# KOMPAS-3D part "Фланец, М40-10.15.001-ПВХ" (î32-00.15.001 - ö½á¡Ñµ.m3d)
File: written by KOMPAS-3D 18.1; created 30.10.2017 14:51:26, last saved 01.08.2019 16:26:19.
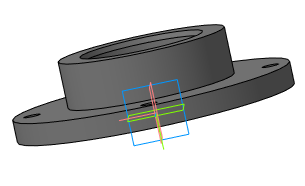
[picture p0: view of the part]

Document properties: Автор: Милов; Организация: Милов; Полное имя файла: D:\Magna\Магна Ins\Магна ins 32\М32-00.15.001 - Фланец.m3d

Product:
- Part/product: Фланец  | designation М40-10.15.001-ПВХ
    Материал: Полипропилен  ГОСТ 26996-86 (density 900 kg/m3)
    Масса: 0.962205
    Раздел спецификации: Детали
    Форматы листов документа: A3
- Part/product: Переходной фланец  | designation М40-00.15.001
    Материал: Полипропилен  ГОСТ 26996-86 (density 900 kg/m3)
    Масса: 0.815286
    Раздел спецификации: Детали
    Форматы листов документа: A3
- Part/product: Переходной фланец  | designation М40-00.15.002
    Материал: Полипропилен  ГОСТ 26996-86 (density 900 kg/m3)
    Масса: 1.3652
    Раздел спецификации: Детали
    Форматы листов документа: A3
- Part/product: Фланец  | designation М32-00.15.001
    Материал: Полипропилен  ГОСТ 26996-86 (density 900 kg/m3)
    Масса: 0.816359
    Раздел спецификации: Детали
    Форматы листов документа: A3
    source file: М32-00.15.001 - Фланец.cdw

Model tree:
1. Эскиз:1
2. Операция вращения:1
     Угол 1 = 360
3. Эскиз:2  (with: Операция вращения:1)
4. Вырезать элемент выдавливания:1
     Расстояние 1 = 30
5. Массив по концентрической сетке:1  (with: Вырезать элемент выдавливания:1, Эскиз:2)  (4 pattern instances)
     Шаг 2 = 360
6. Фаска:1  (with: Операция вращения:1)
     Угол = 45; Длина 1 = 4; Длина 2 = 4
7. Эскиз:3
8. Вырезать элемент выдавливания:2  (labels: Полипропилен  ГОСТ 26996-86; ..\Магна ins 40\3Д\М40-00.15.000 - Корпус М40.a3d)
     Расстояние 1 = 5
9. Вырезать элемент выдавливания:1  (with: Эскиз:2)  (1 pattern instances)
     N 1 = 1; Шаг 1 = 10; Шаг 2 = 360; Номер 1 = 1
10. Эскиз:5  (with: Элемент выдавливания:6, Элемент выдавливания:10)  (labels: FV PPR Редукция 32х20 AA209032020)
11. Элемент выдавливания:1
     Расстояние 2 = 70
12. Эскиз:7  (with: Элемент выдавливания:1)
13. Элемент выдавливания:2
     Расстояние 2 = 70
14. Смещенная плоскость:1  (with: Операция вращения:1)
     Расстояние = 11
15. Эскиз:8  (with: Операция вращения:1)
16. Элемент выдавливания:3
     Расстояние 1 = 12
17. Эскиз:12  (with: Операция вращения:1)
18. Эскиз:14  (with: Элемент выдавливания:3)
19. Элемент выдавливания:6  (with: Эскиз:16, Операция вращения:1)
     Расстояние 2 = 21
20. Элемент выдавливания:8
     Расстояние 2 = 5
21. Элемент выдавливания:9  (with: Операция вращения:1, Эскиз:20)  (labels: Магна Ins 40-L-3-N-1000\Корпус М40 1000\Переходной фланец)
     Расстояние 2 = 20
22. Элемент выдавливания:11  (with: Элемент выдавливания:3, Эскиз:24, Элемент выдавливания:6)
     Расстояние 1 = 11
23. Элемент выдавливания:13  (with: Элемент выдавливания:8)
     Расстояние 1 = 16
24. Фаска:3  (with: Элемент выдавливания:11)
     Угол = 45; Длина 1 = 1; Длина 2 = 1
25. Фаска:4  (with: Элемент выдавливания:13, Эскиз:26, Элемент выдавливания:8)
     Угол = 45; Длина 1 = 1; Длина 2 = 1
26. Элемент выдавливания:14  (with: Эскиз:28, Элемент выдавливания:3, Фаска:4)
     Расстояние 1 = 37
27. Элемент выдавливания:15  (with: Элемент выдавливания:8)
     Расстояние 2 = -16
28. Перпендикулярная плоскость:1  (with: Ось через вершину по объекту:2, Точка:3)  (labels: Корпус М40 1000)
29. Смещенная плоскость:61
     Расстояние = 110
30. Эскиз:42  (with: Элемент выдавливания:1)  (labels: Труба @2~20 PN10@/Полипропилен)
31. Элемент выдавливания:16  (with: Элемент выдавливания:1)  (labels: Труба @2~20 PN10@/Полипропилен)
     Расстояние 2 = 20.2886
32. Эскиз:44  (with: Элемент выдавливания:16)
33. Элемент выдавливания:17
     Расстояние 2 = 46
34. Вырезать элемент выдавливания:1  (with: Эскиз:2)  (1 pattern instances)
     N 1 = 1; Шаг 1 = 10; Шаг 2 = 360; Номер 1 = 1
35. Элемент выдавливания:10  (with: Эскиз:22, Операция вращения:1)
     Расстояние 2 = 11
36. Элемент выдавливания:12
     Расстояние 2 = 22
37. Фаска:2  (with: Элемент выдавливания:12)
     Угол = 45; Длина 1 = 2; Длина 2 = 2
38. Ось конической поверхности:38  (with: Элемент выдавливания:12)
39. Смещенная плоскость:55  (with: Операция вращения:1)
40. ЛСК:38
41. Эскиз:40
42. Присоединительная точка:12
     Перенос X = -5; Расстояние = -5
43. Элемент вращения:12
     Угол 1 = 360
44. Канавка для радиальных уплотнений неподвижных соединений 85x90,0000000000072x2,5 ГОСТ 9833-73
45. Ось конической поверхности:48  (with: Операция вращения:1)
46. Смещенная плоскость:68  (with: Операция вращения:1)
47. ЛСК:48  (with: Плоскость XY, Плоскость ZX, Плоскость ZY, Ось X, Ось Y, Ось Z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)
     Ось X. Y = 1; Ось Y. X = -1; Ось Z. Z = 1
48. Эскиз:46
49. Присоединительная точка:15
     Перенос X = -1.3; Расстояние = -1.3
50. Элемент вращения:15
     Угол 1 = 360
51. Канавка для торцовых уплотнений наружная 215x220x3,6 ГОСТ 9833-73

Expressions: 250/2; 150/2; 215/2; 108.4/2; 185/2
Referenced files in D:\Magna\Магна Ins\Магна ins 40\3Д\: М40-00.15.000 - Корпус М40.a3d
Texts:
  KTE.LIST=9whWkqsxbHSdvvLqOKXQ5a
  KTE.LIST=c9FuUql0M2hEHkNAb1HDAa
  Edge1
  Edge2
